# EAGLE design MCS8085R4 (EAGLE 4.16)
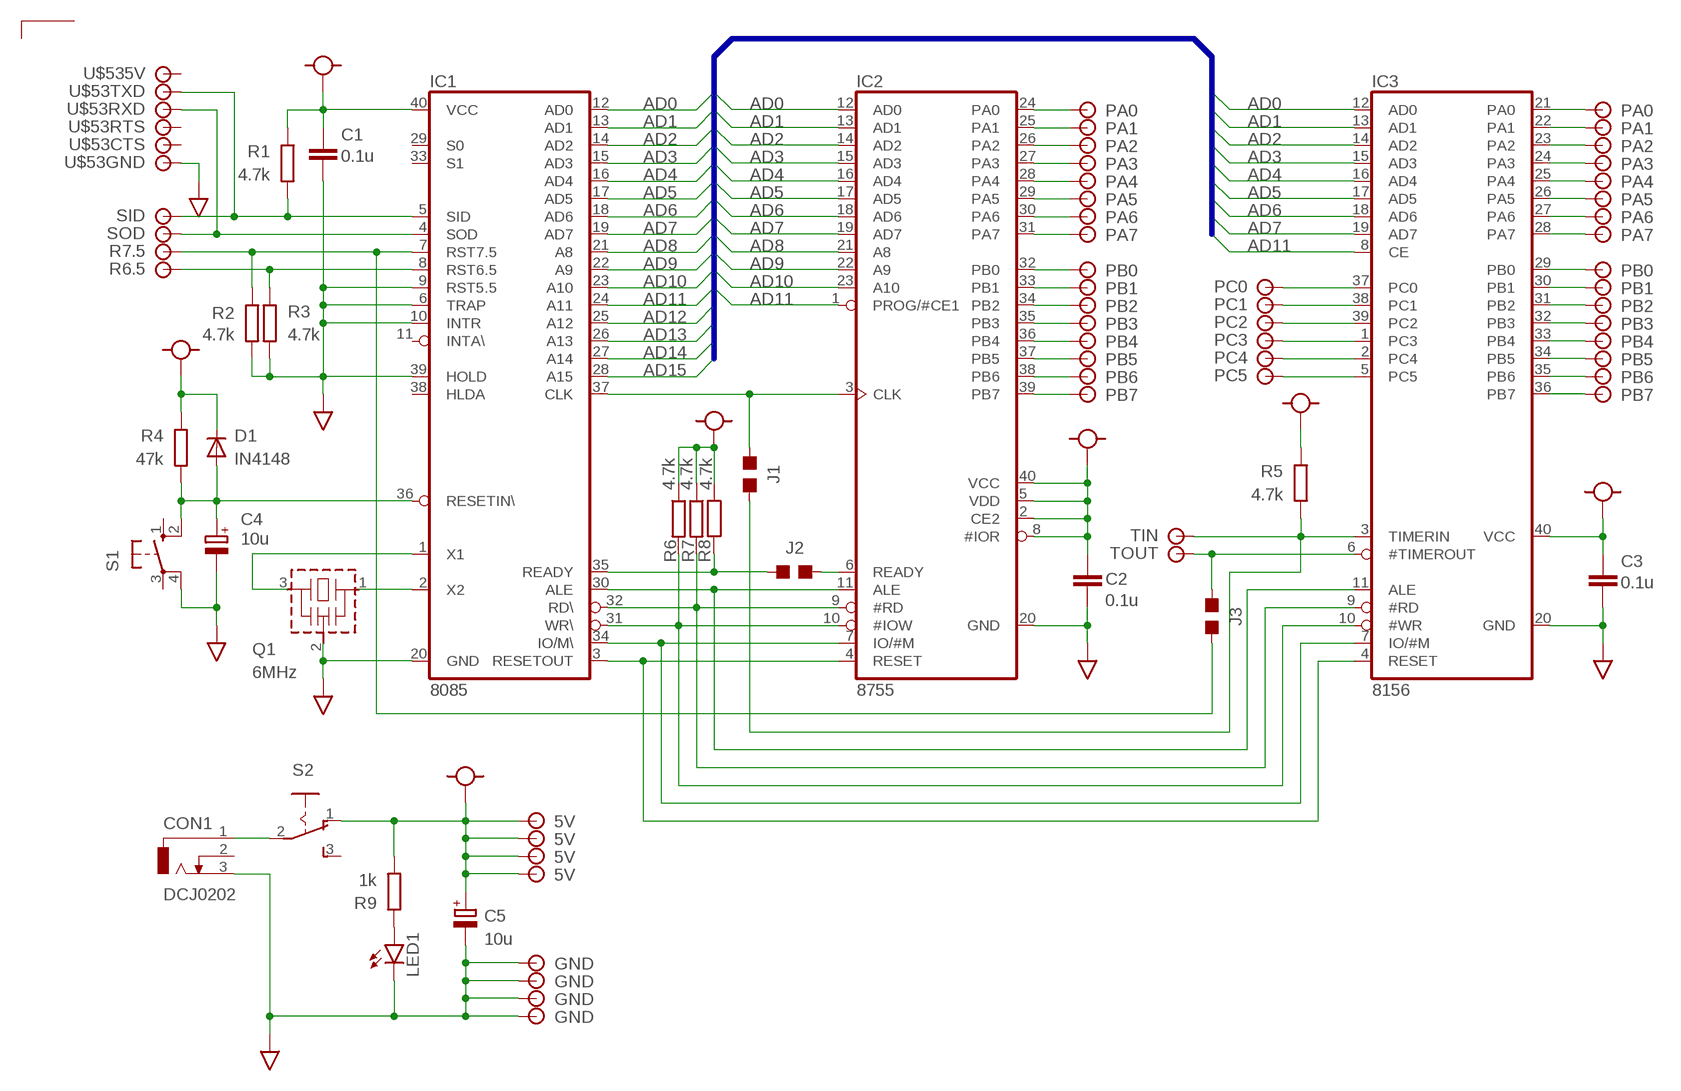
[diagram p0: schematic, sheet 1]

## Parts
C1  0.1u  C-CERAMIC  [C025-025X050]
C2  0.1u  C-CERAMIC  [C025-025X050]
C3  0.1u  C-CERAMIC  [C025-025X050]
C4  10u  C-TANTALUM  [C4518]
C5  10u  C-TANTALUM  [C4518]
CON1  DCJ0202  [DCJ0202]
D1  IN4148  1S1588  [DO41-10]
IC1  8085  8085A  [DIL40]
IC2  8755  8755A  [DIL40]
IC3  8156  [DIL40]
J1  SOLPAD  [SOLPAD]
J2  SOLPAD  [SOLPAD]
J3  SOLPAD  [SOLPAD]
LED1  LED3MM  [LED3MM]
Q1  6MHz  CSTLA_T  [CSTLA_T]
R1  4.7k  R1/8W  [0207/10]
R2  4.7k  R1/8W  [0207/10]
R3  4.7k  R1/8W  [0207/10]
R4  47k  R1/8W  [0207/10]
R5  4.7k  R1/8W  [0207/10]
R6  4.7k  R1/8W  [0207/10]
R7  4.7k  R1/8W  [0207/10]
R8  4.7k  R1/8W  [0207/10]
R9  1k  R1/8W  [0207/10]
S1  SW-TACT  [B3F-10XX]
S2  255SB  [255SB]
U$1  PA0  LAND-NN  [LAND-NN]
U$2  PA0  LAND-NN  [LAND-NN]
U$3  PA1  LAND-NN  [LAND-NN]
U$4  PA1  LAND-NN  [LAND-NN]
U$5  PA2  LAND-NN  [LAND-NN]
U$6  PA2  LAND-NN  [LAND-NN]
U$7  PA3  LAND-NN  [LAND-NN]
U$8  PA3  LAND-NN  [LAND-NN]
U$9  PA4  LAND-NN  [LAND-NN]
U$10  PA4  LAND-NN  [LAND-NN]
U$11  PA5  LAND-NN  [LAND-NN]
U$12  PA5  LAND-NN  [LAND-NN]
U$13  SID  LAND-NN  [LAND-NN]
U$14  PA6  LAND-NN  [LAND-NN]
U$15  PA6  LAND-NN  [LAND-NN]
U$16  SOD  LAND-NN  [LAND-NN]
U$17  PA7  LAND-NN  [LAND-NN]
U$18  PA7  LAND-NN  [LAND-NN]
U$19  R7.5  LAND-NN  [LAND-NN]
U$20  R6.5  LAND-NN  [LAND-NN]
U$21  PB0  LAND-NN  [LAND-NN]
U$22  PB0  LAND-NN  [LAND-NN]
U$23  PB1  LAND-NN  [LAND-NN]
U$24  PC0  LAND-NN  [LAND-NN]
U$25  PB1  LAND-NN  [LAND-NN]
U$26  PB2  LAND-NN  [LAND-NN]
U$27  PC1  LAND-NN  [LAND-NN]
U$28  PB2  LAND-NN  [LAND-NN]
U$29  PB3  LAND-NN  [LAND-NN]
U$30  PC2  LAND-NN  [LAND-NN]
U$31  PB3  LAND-NN  [LAND-NN]
U$32  PB4  LAND-NN  [LAND-NN]
U$33  PC3  LAND-NN  [LAND-NN]
U$34  PB4  LAND-NN  [LAND-NN]
U$35  PB5  LAND-NN  [LAND-NN]
U$36  PC4  LAND-NN  [LAND-NN]
U$37  PB5  LAND-NN  [LAND-NN]
U$38  PB6  LAND-NN  [LAND-NN]
U$39  PC5  LAND-NN  [LAND-NN]
U$40  PB6  LAND-NN  [LAND-NN]
U$41  PB7  LAND-NN  [LAND-NN]
U$42  PB7  LAND-NN  [LAND-NN]
U$43  TIN  LAND-NN  [LAND-NN]
U$44  TOUT  LAND-NN  [LAND-NN]
U$45  5V  LAND-NN  [LAND-NN]
U$46  5V  LAND-NN  [LAND-NN]
U$47  5V  LAND-NN  [LAND-NN]
U$48  5V  LAND-NN  [LAND-NN]
U$49  GND  LAND-NN  [LAND-NN]
U$50  GND  LAND-NN  [LAND-NN]
U$51  GND  LAND-NN  [LAND-NN]
U$52  GND  LAND-NN  [LAND-NN]
U$53  TTL-232R-5V  [TTL-232R-5V]

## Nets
AD0: IC1.12(AD0) IC2.12(AD0) IC3.12(AD0)
AD1: IC1.13(AD1) IC2.13(AD1) IC3.13(AD1)
AD2: IC1.14(AD2) IC2.14(AD2) IC3.14(AD2)
AD3: IC1.15(AD3) IC2.15(AD3) IC3.15(AD3)
AD4: IC1.16(AD4) IC2.16(AD4) IC3.16(AD4)
AD5: IC1.17(AD5) IC2.17(AD5) IC3.17(AD5)
AD6: IC1.18(AD6) IC2.18(AD6) IC3.18(AD6)
AD7: IC1.19(AD7) IC2.19(AD7) IC3.19(AD7)
AD8: IC1.21(A8) IC2.21(A8)
AD9: IC1.22(A9) IC2.22(A9)
AD10: IC1.23(A10) IC2.23(A10)
AD11: IC1.24(A11) IC2.1(PROG/#CE1) IC3.8(CE)
AD12: IC1.25(A12)
AD13: IC1.26(A13)
AD14: IC1.27(A14)
AD15: IC1.28(A15)
GND: C1.2 C2.2 C3.2 C4.- C5.- CON1.3 IC1.6(TRAP) IC1.9(RST5.5) IC1.10(INTR) IC1.20(GND) IC1.39(HOLD) IC2.20(GND) IC3.20(GND) LED1.K(C) Q1.2(VSS) R2.2 R3.2 S1.4(P1) U$49.P U$50.P U$51.P U$52.P U$53.1
N$1: IC1.34(IO/M\) IC2.7(IO/#M) IC3.7(IO/#M)
N$2: IC1.1(X1) Q1.3
N$3: IC1.2(X2) Q1.1
N$4: IC1.31(WR\) IC2.10(#IOW) IC3.10(#WR) R6.2
N$5: IC1.32(RD\) IC2.9(#RD) IC3.9(#RD) R7.2
N$6: IC1.37(CLK) IC2.3(CLK) J1.1
N$7: IC1.3(RESETOUT) IC2.4(RESET) IC3.4(RESET)
N$8: IC1.30(ALE) IC2.11(ALE) IC3.11(ALE)
N$9: CON1.1 S2.2(P)
N$10: IC1.35(READY) J2.1 R8.2
N$11: IC2.6(READY) J2.2
N$12: LED1.A R9.1
N$13: IC2.24(PA0) U$1.P
N$14: IC2.25(PA1) U$3.P
N$15: IC2.26(PA2) U$5.P
N$16: IC2.27(PA3) U$7.P
N$17: IC2.28(PA4) U$9.P
N$18: IC1.8(RST6.5) R3.1 U$20.P
N$19: IC2.29(PA5) U$11.P
N$20: IC2.30(PA6) U$14.P
N$21: IC2.31(PA7) U$17.P
N$22: IC2.32(PB0) U$21.P
N$23: IC2.33(PB1) U$23.P
N$24: IC1.7(RST7.5) J3.2 R2.1 U$19.P
N$25: IC2.34(PB2) U$26.P
N$26: IC2.35(PB3) U$29.P
N$27: IC2.36(PB4) U$32.P
N$28: IC2.37(PB5) U$35.P
N$29: IC2.38(PB6) U$38.P
N$30: IC2.39(PB7) U$41.P
N$31: IC3.21(PA0) U$2.P
N$32: IC3.22(PA1) U$4.P
N$33: IC3.23(PA2) U$6.P
N$34: C4.+ D1.A IC1.36(RESETIN\) R4.2 S1.2(S1)
N$35: IC3.24(PA3) U$8.P
N$36: IC3.25(PA4) U$10.P
N$37: IC3.26(PA5) U$12.P
N$38: IC3.27(PA6) U$15.P
N$39: IC3.28(PA7) U$18.P
N$40: IC3.29(PB0) U$22.P
N$41: IC3.30(PB1) U$25.P
N$42: IC3.31(PB2) U$28.P
N$43: IC3.32(PB3) U$31.P
N$44: IC3.33(PB4) U$34.P
N$45: IC3.34(PB5) U$37.P
N$46: IC3.35(PB6) U$40.P
N$47: IC3.36(PB7) U$42.P
N$48: IC3.5(PC5) U$39.P
N$49: IC3.2(PC4) U$36.P
N$50: IC3.1(PC3) U$33.P
N$51: IC3.39(PC2) U$30.P
N$52: IC3.38(PC1) U$27.P
N$53: IC3.37(PC0) U$24.P
N$54: IC3.3(TIMERIN) J1.2 R5.1 U$43.P
N$55: IC3.6(#TIMEROUT) J3.1 U$44.P
SID: IC1.5(SID) R1.2 U$13.P U$53.4
SOD: IC1.4(SOD) U$16.P U$53.5
VCC: C1.1 C2.1 C3.1 C5.+ D1.C IC1.40(VCC) IC2.2(CE2) IC2.5(VDD) IC2.8(#IOR) IC2.40(VCC) IC3.40(VCC) R1.1 R4.1 R5.2 R6.1 R7.1 R8.1 R9.2 S2.1(O) U$45.P U$46.P U$47.P U$48.P
Unconnected: CON1.2 IC1.11(INTA\) IC1.29(S0) IC1.33(S1) IC1.38(HLDA) S1.1(S) S1.3(P) S2.3(S) U$53.2 U$53.3 U$53.6

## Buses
AD[0..15]

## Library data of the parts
C1-C3 = olimex-devices:C-CERAMIC: Ceramic Conenser
C4 C5 = olimex-devices:C-TANTALUM: Tantalum Condenser
CON1 = olimex-devices:DCJ0202: DC POWER JACK Source: DCJ0202.pdf
D1 = olimex-devices:1S1588: Small Signal Diode
IC1 = olimex-devices:8085A
IC2 = olimex-devices:8755A
IC3 = olimex-devices:8156
J1-J3 = olimex-devices:SOLPAD
LED1 = olimex-devices:LED3MM: LED
Q1 = olimex-devices:CSTLA_T: Ceramic resonator 10.01 to 13.00 MHz
R1-R9 = olimex-devices:R1/8W: Carbon Resistor
S1 = olimex-devices:SW-TACT: Tact Switch (Small)
S2 = olimex-devices:255SB: SLIDING SWITCH distributor Buerklin, 11G810
U$1-U$52 = olimex-devices:LAND-NN
U$53 = olimex-devices:TTL-232R-5V

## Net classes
1 GND: width 0.61 mm
2 VCC: width 0.61 mm

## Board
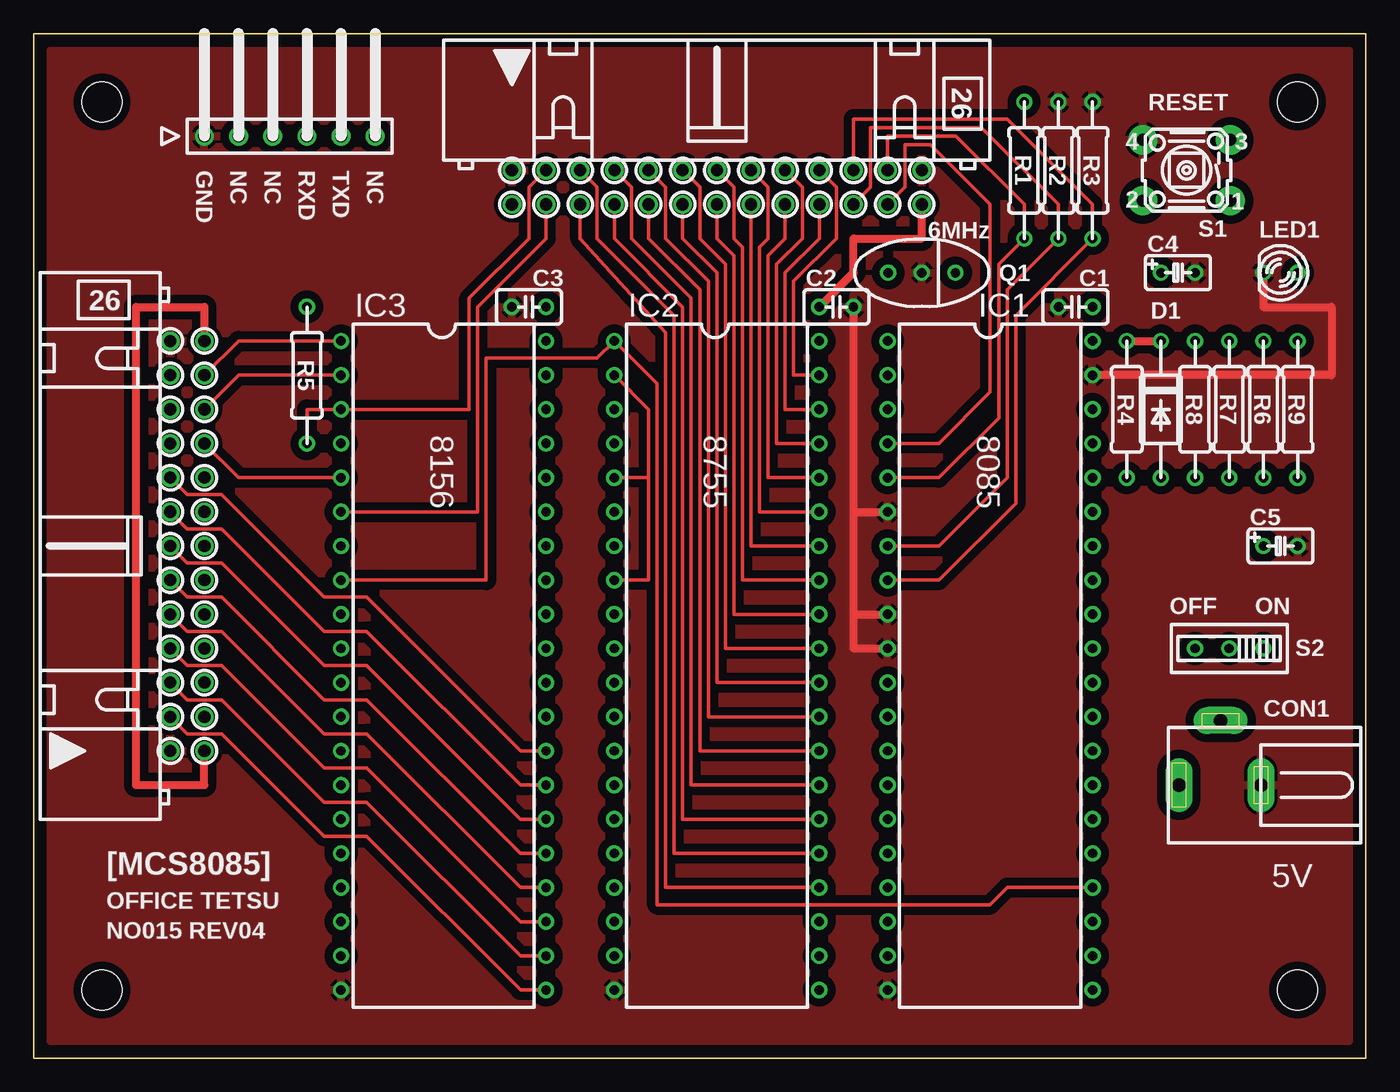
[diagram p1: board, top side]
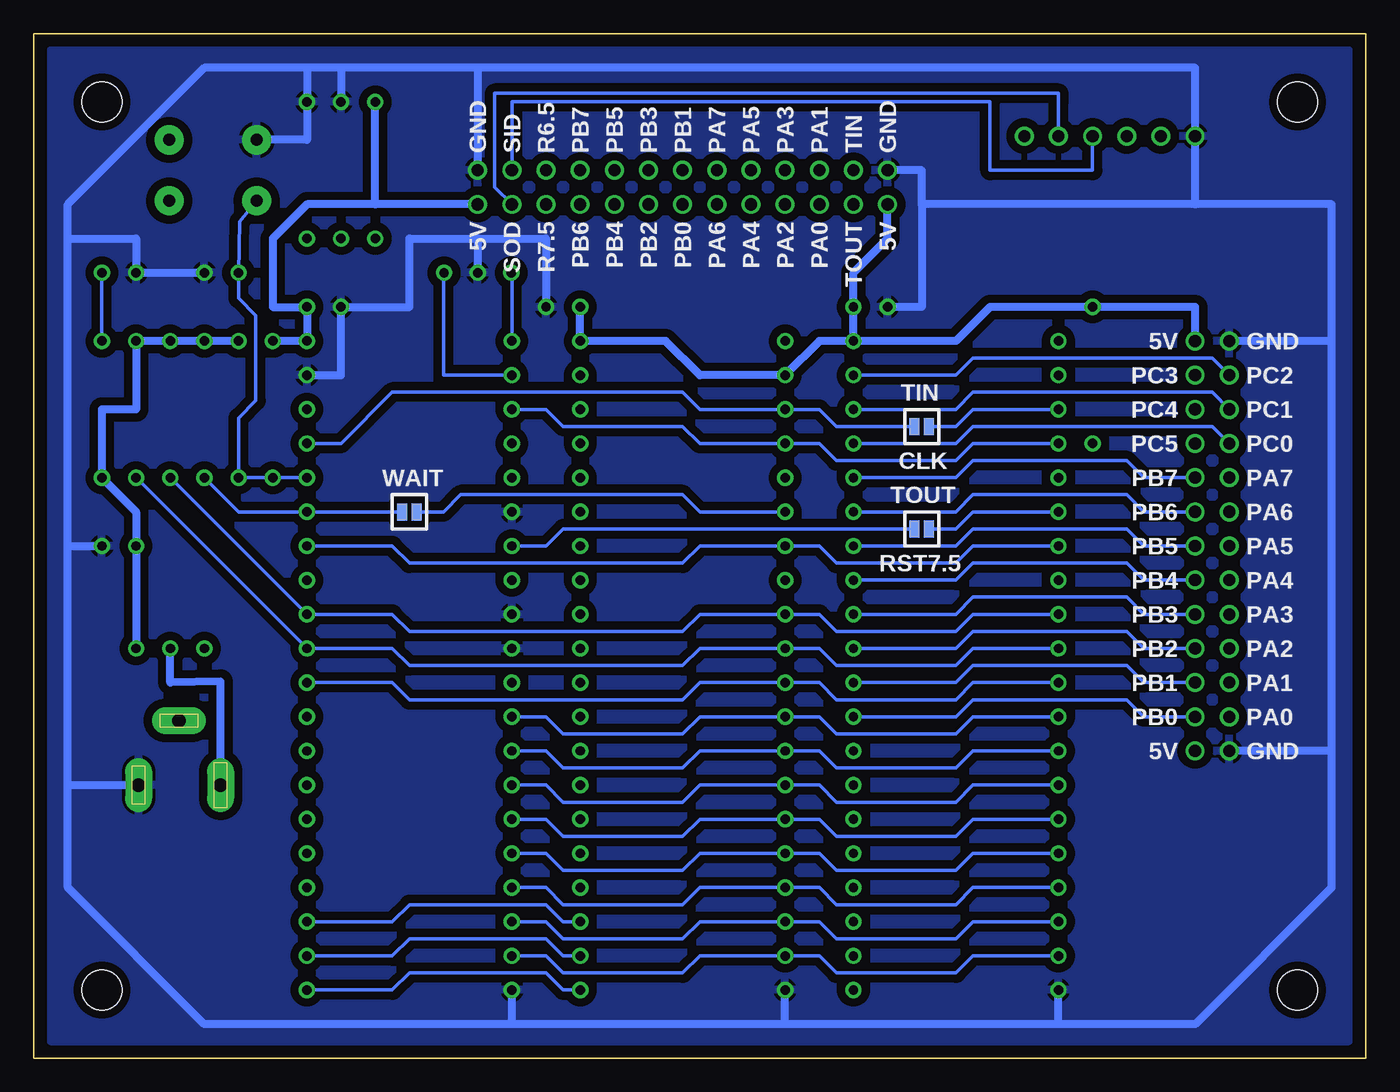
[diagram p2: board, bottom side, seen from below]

Size 99.06 x 76.2 mm. Coordinates in mm from the lower left corner, seen from the top.
Outline: 99.06,76.2 0,76.2 0,0 99.06,0 99.06,76.2
Copper layers (1*16): Top 0.035mm / dielectric 1.5mm / Bottom 0.035mm
Design rules "SeeedStudio": minimum track width 6mil, minimum drill 12mil, track to track 6mil, track to pad 6mil, pad to pad 6mil, via to via 6mil, smd to smd 0mil, copper to edge 10mil, drill to drill 10mil, minimum pad ring 10mil, minimum via ring 6mil, stop-mask expansion 2mil, vias tented up to drill 25mil, thermal gap 10mil
Holes 3 mm at 5.08,5.08 93.98,5.08 5.08,71.12 93.98,71.12

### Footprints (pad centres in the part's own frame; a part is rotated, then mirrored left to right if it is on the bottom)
C025-025X050 = drill 0.7 round: 1 -1.27,0; 2 1.27,0
C4518 = drill 0.7 round: + -1.27,0; - 1.27,0
DCJ0202 = drill 1 pad 2 long: 1 0,3.1; 2 4.8,0; 3 0,-3
DO41-10 = drill 0.7 round: A 5.08,0; C -5.08,0
DIL40 = drill 0.7 round: 1 -24.13,-7.62; 2 -21.59,-7.62; 3 -19.05,-7.62; 4 -16.51,-7.62; 5 -13.97,-7.62; 6 -11.43,-7.62; 7 -8.89,-7.62; 8 -6.35,-7.62; 9 -3.81,-7.62; 10 -1.27,-7.62; 11 1.27,-7.62; 12 3.81,-7.62; 13 6.35,-7.62; 14 8.89,-7.62; 15 11.43,-7.62; 16 13.97,-7.62; 17 16.51,-7.62; 18 19.05,-7.62; 19 21.59,-7.62; 20 24.13,-7.62; 21 24.13,7.62; 22 21.59,7.62; 23 19.05,7.62; 24 16.51,7.62; 25 13.97,7.62; 26 11.43,7.62; 27 8.89,7.62; 28 6.35,7.62; 29 3.81,7.62; 30 1.27,7.62; 31 -1.27,7.62; 32 -3.81,7.62; 33 -6.35,7.62; 34 -8.89,7.62; 35 -11.43,7.62; 36 -13.97,7.62; 37 -16.51,7.62; 38 -19.05,7.62; 39 -21.59,7.62; 40 -24.13,7.62
SOLPAD = smd 0.736 x 1.27: 1 -0.54,0; 2 0.54,0
LED3MM = drill 0.7 round: A -1.27,0; K 1.27,0
CSTLA_T = drill 0.7 round: 1 -2.5,0; 2 0,0; 3 2.5,0
0207/10 = drill 0.7 round: 1 -5.08,0; 2 5.08,0
B3F-10XX = drill 0.9 pad 2.184 round: 1 -3.251,2.261; 2 3.251,2.261; 3 -3.251,-2.261; 4 3.251,-2.261
255SB = drill 0.7 round: 1 -2.54,0; 2 0,0; 3 2.54,0
LAND-NN = drill 0.9 round: P 0,0
TTL-232R-5V = drill 0.9 round: 1 -6.35,0; 2 -3.81,0; 3 -1.27,0; 4 1.27,0; 5 3.81,0; 6 6.35,0

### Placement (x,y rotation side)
C1  77.47,55.88 180 top
C2  59.69,55.88 0 top
C3  36.83,55.88 180 top
C4  85.09,58.42 0 top
C5  92.71,38.1 0 top
CON1  88.27,20.32 90 top
D1  83.82,48.26 270 top
IC1  71.12,29.21 270 top
IC2  50.8,29.21 270 top
IC3  30.48,29.21 270 top
J1  33.02,46.99 0 bottom
J2  71.12,40.64 0 bottom
J3  33.02,39.37 180 bottom
LED1  92.71,58.42 180 top
Q1  66.04,58.42 180 top
R1  73.66,66.04 270 top
R2  76.2,66.04 90 top
R3  78.74,66.04 90 top
R4  81.28,48.26 270 top
R5  20.32,50.8 90 top
R6  91.44,48.26 270 top
R7  88.9,48.26 270 top
R8  86.36,48.26 270 top
R9  93.98,48.26 270 top
S1  85.72,66.04 180 top
S2  88.9,30.48 180 top
U$1  40.64,63.5 90 top
U$2  10.16,25.4 180 top
U$3  40.64,66.04 270 top
U$4  10.16,27.94 180 top
U$5  43.18,63.5 270 top
U$6  10.16,30.48 180 top
U$7  43.18,66.04 270 top
U$8  10.16,33.02 180 top
U$9  45.72,63.5 270 top
U$10  10.16,35.56 180 top
U$11  45.72,66.04 270 top
U$12  10.16,38.1 180 top
U$13  63.5,66.04 90 top
U$14  48.26,63.5 270 top
U$15  10.16,40.64 180 top
U$16  63.5,63.5 90 top
U$17  48.26,66.04 270 top
U$18  10.16,43.18 180 top
U$19  60.96,63.5 270 top
U$20  60.96,66.04 90 top
U$21  50.8,63.5 270 top
U$22  12.7,25.4 0 top
U$23  50.8,66.04 90 top
U$24  10.16,45.72 180 top
U$25  12.7,27.94 0 top
U$26  53.34,63.5 90 top
U$27  10.16,48.26 180 top
U$28  12.7,30.48 0 top
U$29  53.34,66.04 90 top
U$30  10.16,50.8 180 top
U$31  12.7,33.02 0 top
U$32  55.88,63.5 90 top
U$33  12.7,50.8 0 top
U$34  12.7,35.56 0 top
U$35  55.88,66.04 90 top
U$36  12.7,48.26 0 top
U$37  12.7,38.1 0 top
U$38  58.42,63.5 90 top
U$39  12.7,45.72 0 top
U$40  12.7,40.64 0 top
U$41  58.42,66.04 90 top
U$42  12.7,43.18 0 top
U$43  38.1,66.04 90 top
U$44  38.1,63.5 90 top
U$45  35.56,63.5 90 top
U$46  12.7,53.34 0 top
U$47  12.7,22.86 0 top
U$48  66.04,63.5 90 top
U$49  66.04,66.04 90 top
U$50  10.16,22.86 180 top
U$51  10.16,53.34 180 top
U$52  35.56,66.04 270 top
U$53  19.05,68.58 0 top

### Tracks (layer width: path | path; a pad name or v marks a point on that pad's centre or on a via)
AD0
  Bottom 0.254: IC3.12 29.21,25.4 30.48,24.13 39.37,24.13 40.64,25.4 IC2.12 49.53,25.4 50.8,24.13 59.69,24.13 60.96,25.4 IC1.12
AD1
  Bottom 0.254: IC3.13 29.21,22.86 30.48,21.59 39.37,21.59 40.64,22.86 IC2.13 49.53,22.86 50.8,21.59 59.69,21.59 60.96,22.86 IC1.13
AD2
  Bottom 0.254: IC3.14 29.21,20.32 30.48,19.05 39.37,19.05 40.64,20.32 IC2.14 49.53,20.32 50.8,19.05 59.69,19.05 60.96,20.32 IC1.14
AD3
  Bottom 0.254: IC3.15 29.21,17.78 30.48,16.51 39.37,16.51 40.64,17.78 IC2.15 49.53,17.78 50.8,16.51 59.69,16.51 60.96,17.78 IC1.15
AD4
  Bottom 0.254: IC3.16 29.21,15.24 30.48,13.97 39.37,13.97 40.64,15.24 IC2.16 49.53,15.24 50.8,13.97 59.69,13.97 60.96,15.24 IC1.16
AD5
  Bottom 0.254: IC3.17 29.21,12.7 30.48,11.43 39.37,11.43 40.64,12.7 IC2.17 49.53,12.7 50.8,11.43 59.69,11.43 60.96,12.7 IC1.17
AD6
  Bottom 0.254: IC3.18 29.21,10.16 30.48,8.89 39.37,8.89 40.64,10.16 IC2.18 49.53,10.16 50.8,8.89 59.69,8.89 60.96,10.16 IC1.18
AD7
  Bottom 0.254: IC3.19 29.21,7.62 30.48,6.35 39.37,6.35 40.64,7.62 IC2.19 49.53,7.62 50.8,6.35 59.69,6.35 60.96,7.62 IC1.19
AD8
  Bottom 0.254: IC2.21 59.69,5.08 60.96,6.35 71.12,6.35 72.39,5.08 IC1.21
AD9
  Bottom 0.254: IC2.22 59.69,7.62 60.96,8.89 71.12,8.89 72.39,7.62 IC1.22
AD10
  Bottom 0.254: IC2.23 59.69,10.16 60.96,11.43 71.12,11.43 72.39,10.16 IC1.23
AD11
  Top 0.254: IC3.8 33.66,35.56 33.66,52.07 41.91,52.07 IC2.1 46.35,50.16 46.35,11.43 71.12,11.43 72.39,12.7 IC1.24
GND
  Top 0.61: 60.96,33.02 60.96,30.48 IC1.10 | 60.96,40.64 60.96,33.02 | C2.2 60.96,40.64 | 60.96,33.02 IC1.9 | 60.96,40.64 IC1.6 | IC1.39 96.52,50.8 96.52,55.88 91.44,55.88 LED1.K
  Bottom 0.61: 66.04,60.96 Q1.2 | 76.2,73.66 78.74,73.66 | 78.74,73.66 86.36,73.66 96.52,63.5 96.52,60.96 | 96.52,20.32 96.52,12.7 86.36,2.54 63.5,2.54 | 96.52,20.32 96.52,38.1 | 96.52,38.1 96.52,60.96 | 63.5,2.54 IC1.20 | 22.86,2.54 12.7,2.54 2.54,12.7 2.54,22.86 | 2.54,22.86 2.54,53.34 | 2.54,53.34 2.54,63.5 12.7,63.5 | 66.04,73.66 12.7,73.66 U$53.1 12.7,63.5 | 66.04,73.66 76.2,73.66 | 2.54,53.34 U$51.P | 2.54,22.86 U$50.P | C2.2 60.96,60.96 66.04,60.96 | 22.86,2.54 IC3.20 | 22.86,2.54 43.18,2.54 | 43.18,2.54 63.5,2.54 | 43.18,2.54 IC2.20 | 66.04,73.66 U$49.P | C3.2 33.02,55.88 33.02,63.5 | 33.02,63.5 33.02,66.04 U$52.P | IC1.39 76.2,50.8 C1.2 71.12,55.88 71.12,60.96 66.04,60.96 | 76.2,73.66 R2.2 | 78.74,73.66 R3.2 78.74,68.3 S1.4 | 96.52,20.32 CON1.3 | 96.52,60.96 91.44,60.96 LED1.K C4.- | 12.7,63.5 33.02,63.5 | 96.52,38.1 C5.-
  pour Bottom (isolate 0.61): 1.27,74.93 97.79,74.93 97.79,1.27 1.27,1.27
  pour Top (isolate 0.61): 1.27,74.93 97.79,74.93 97.79,1.27 1.27,1.27
N$1
  Bottom 0.254: IC3.7 29.21,38.1 30.48,36.83 39.37,36.83 40.64,38.1 IC2.7 49.53,38.1 50.8,36.83 71.12,36.83 72.39,38.1 IC1.34
N$2
  Bottom 0.254: Q1.3 63.5,58.42 IC1.1
N$3
  Bottom 0.254: IC1.2 68.58,50.8 68.58,58.42 Q1.1
N$4
  Bottom 0.254: IC3.10 29.21,30.48 30.48,29.21 39.37,29.21 40.64,30.48 IC2.10 49.53,30.48 50.8,29.21 71.12,29.21 72.39,30.48 IC1.31 R6.2
N$5
  Bottom 0.254: IC3.9 29.21,33.02 30.48,31.75 39.37,31.75 40.64,33.02 IC2.9 49.53,33.02 50.8,31.75 71.12,31.75 72.39,33.02 IC1.32 R7.2
N$6
  Bottom 0.254: IC1.37 76.2,45.72 72.39,49.53 50.8,49.53 49.53,48.26 IC2.3 40.64,48.26 39.37,46.99 J1.1
N$7
  Bottom 0.254: IC3.4 29.21,45.72 30.48,44.45 39.37,44.45 40.64,45.72 IC2.4 49.53,45.72 50.8,46.99 59.69,46.99 60.96,48.26 IC1.3
N$8
  Bottom 0.254: IC3.11 29.21,27.94 30.48,26.67 39.37,26.67 40.64,27.94 IC2.11 49.53,27.94 50.8,26.67 71.12,26.67 72.39,27.94 IC1.30
N$9
  Bottom 0.61: CON1.1 85.17,28.02 88.9,27.94 S2.2
N$10
  Bottom 0.254: J2.1 IC1.35 83.82,40.64 R8.2
N$11
  Bottom 0.254: IC2.6 49.53,40.64 50.8,41.91 67.31,41.91 68.58,40.64 J2.2
N$12
  Bottom 0.254: R9.1 LED1.A
N$13
  Top 0.254: IC2.24 46.99,12.7 46.99,53.98 40.64,60.96 U$1.P
N$14
  Top 0.254: IC2.25 47.62,15.24 47.62,55.24 41.91,60.96 41.91,64.77 U$3.P
N$15
  Top 0.254: IC2.26 48.26,17.78 48.26,55.88 43.18,60.96 U$5.P
N$16
  Top 0.254: IC2.27 48.9,20.32 48.9,56.52 44.45,60.96 44.45,64.77 U$7.P
N$17
  Top 0.254: IC2.28 49.53,22.86 49.53,57.15 45.72,60.96 U$9.P
N$18
  Top 0.254: IC1.8 67.31,35.56 73.03,41.27 73.03,55.24 R3.1 78.74,63.5 72.39,69.85 60.96,69.85 U$20.P
N$19
  Top 0.254: IC2.29 50.16,25.4 50.16,57.78 46.99,60.96 46.99,64.77 U$11.P
N$20
  Top 0.254: IC2.30 50.8,27.94 50.8,58.42 48.26,60.96 U$14.P
N$21
  Top 0.254: IC2.31 51.44,30.48 51.44,59.05 49.53,60.96 49.53,64.77 U$17.P
N$22
  Top 0.254: IC2.32 52.07,33.02 52.07,59.69 50.8,60.96 U$21.P
N$23
  Top 0.254: IC2.33 52.7,35.56 52.7,60.33 52.07,60.96 52.07,64.77 U$23.P
N$24
  Top 0.254: IC1.7 67.31,38.1 72.39,43.18 72.39,57.15 R2.1 76.2,63.5 70.48,69.22 62.23,69.22 62.23,64.77 U$19.P
  Bottom 0.254: J3.2 59.69,39.37 60.96,38.1 IC1.7
N$25
  Top 0.254: IC2.34 53.34,38.1 U$26.P
N$26
  Top 0.254: IC2.35 53.98,40.64 53.98,60.33 54.61,60.96 54.61,64.77 U$29.P
N$27
  Top 0.254: IC2.36 54.61,43.18 54.61,59.69 55.88,60.96 U$32.P
N$28
  Top 0.254: IC2.37 55.24,45.72 55.24,59.05 57.15,60.96 57.15,64.77 U$35.P
N$29
  Top 0.254: IC2.38 55.88,48.26 55.88,58.42 58.42,60.96 U$38.P
N$30
  Top 0.254: IC2.39 56.52,50.8 56.52,57.78 59.69,60.96 59.69,64.77 U$41.P
N$31
  Top 0.254: U$2.P 11.43,24.13 13.97,24.13 21.59,16.51 24.77,16.51 36.2,5.08 IC3.21
N$32
  Top 0.254: U$4.P 11.43,26.67 13.97,26.67 21.59,19.05 24.77,19.05 36.2,7.62 IC3.22
N$33
  Top 0.254: U$6.P 11.43,29.21 13.97,29.21 21.59,21.59 24.77,21.59 36.2,10.16 IC3.23
N$34
  Bottom 0.254: IC1.36 R4.2 D1.A 83.82,47.62 82.55,48.9 82.55,55.24 83.82,56.52 C4.+ 83.74,62.23 S1.2
N$35
  Top 0.254: U$8.P 11.43,31.75 13.97,31.75 21.59,24.13 24.77,24.13 36.2,12.7 IC3.24
N$36
  Top 0.254: U$10.P 11.43,34.29 13.97,34.29 21.59,26.67 24.77,26.67 36.2,15.24 IC3.25
N$37
  Top 0.254: U$12.P 11.43,36.83 13.97,36.83 21.59,29.21 24.77,29.21 36.2,17.78 IC3.26
N$38
  Top 0.254: U$15.P 11.43,39.37 13.97,39.37 21.59,31.75 24.77,31.75 36.2,20.32 IC3.27
N$39
  Top 0.254: U$18.P 11.43,41.91 13.97,41.91 21.59,34.29 24.77,34.29 36.2,22.86 IC3.28
N$40
  Bottom 0.254: U$22.P 16.51,25.4 17.78,26.67 29.21,26.67 30.48,25.4 IC3.29
N$41
  Bottom 0.254: U$25.P 16.51,27.94 17.78,29.21 29.21,29.21 30.48,27.94 IC3.30
N$42
  Bottom 0.254: U$28.P 16.51,30.48 17.78,31.75 29.21,31.75 30.48,30.48 IC3.31
N$43
  Bottom 0.254: U$31.P 16.51,33.02 17.78,34.29 29.21,34.29 30.48,33.02 IC3.32
N$44
  Bottom 0.254: U$34.P 16.51,35.56 17.78,36.83 29.21,36.83 30.48,35.56 IC3.33
N$45
  Bottom 0.254: IC3.34 30.48,38.1 29.21,39.37 17.78,39.37 16.51,38.1 U$37.P
N$46
  Bottom 0.254: U$40.P 16.51,40.64 17.78,41.91 29.21,41.91 30.48,40.64 IC3.35
N$47
  Bottom 0.254: U$42.P 16.51,43.18 17.78,44.45 29.21,44.45 30.48,43.18 IC3.36
N$48
  Top 0.254: U$39.P 15.24,43.18 IC3.5
N$49
  Top 0.254: U$36.P 15.24,50.8 IC3.2
N$50
  Top 0.254: U$33.P 15.24,53.34 IC3.1
N$51
  Bottom 0.254: U$30.P 11.43,52.07 29.21,52.07 30.48,50.8 IC3.39
N$52
  Bottom 0.254: U$27.P 11.43,49.53 29.21,49.53 30.48,48.26 IC3.38
N$53
  Bottom 0.254: U$24.P 11.43,46.99 29.21,46.99 30.48,45.72 IC3.37
N$54
  Top 0.254: U$43.P 36.83,64.77 36.83,60.96 32.38,56.52 32.38,48.26 IC3.3 20.32,48.26 R5.1
  Bottom 0.254: IC3.3 29.21,48.26 30.48,46.99 J1.2
N$55
  Top 0.254: IC3.6 33.02,40.64 33.02,55.88 38.1,60.96 U$44.P
  Bottom 0.254: J3.1 30.48,39.37 29.21,40.64 IC3.6
SID
  Top 0.254: IC1.5 67.31,43.18 71.75,47.62 71.75,59.05 R1.2 73.66,63.5 68.58,68.58 63.5,68.58 U$13.P
  Bottom 0.254: U$53.4 20.32,66.04 27.94,66.04 27.94,71.12 63.5,71.12 U$13.P
SOD
  Top 0.254: IC1.4 67.31,45.72 71.12,49.53 71.12,63.5 66.67,67.94 64.77,67.94 64.77,64.77 U$16.P
  Bottom 0.254: 22.86,71.12 U$53.5 22.86,71.75 64.77,71.75 64.77,64.77 U$16.P
VCC
  Top 0.254: IC2.2 45.72,48.26 45.72,43.18 | 45.72,43.18 45.72,35.56 IC2.8 | 45.72,43.18 IC2.5
  Top 0.61: C2.1 60.96,58.42 60.96,60.96 66.04,60.96 U$48.P | U$47.P 12.7,20.32 7.62,20.32 7.62,55.88 12.7,55.88 U$46.P | R4.1 D1.C
  Bottom 0.61: R4.1 IC1.40 C1.1 81.28,55.88 81.28,60.96 78.74,63.5 73.66,63.5 | IC3.40 C3.1 38.1,58.42 35.56,60.96 U$45.P | IC3.40 40.64,53.34 IC2.2 49.53,50.8 52.07,53.34 IC2.40 C2.1 | U$46.P 12.7,55.88 R5.2 27.94,55.88 30.48,53.34 IC3.40 | U$48.P 73.66,63.5 | 73.66,63.5 R1.1 | D1.C R8.1 R7.1 R6.1 91.44,48.26 93.98,48.26 R9.2 91.44,40.64 C5.+ S2.1

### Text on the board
tPlace: 26 | RESET | GND | NC | NC | RXD | TXD | NC | 26 | OFF | ON | [MCS8085] | 5V | OFFICE TETSU | NO015 REV04
bPlace: TIN | CLK | WAIT | TOUT | RST7.5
